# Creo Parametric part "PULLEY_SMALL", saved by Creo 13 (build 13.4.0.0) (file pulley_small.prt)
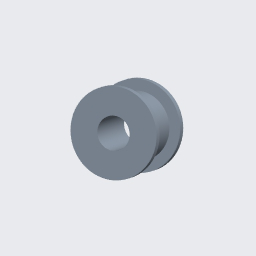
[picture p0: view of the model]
Units: millimeter Newton Second (mmNs); MM, TONNE, SECS

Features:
  1. datum plane "RIGHT"
  2. datum plane "TOP"
  3. datum plane "FRONT"
  4. coordinate system
  5. protrusion
  6. protrusion
  7. protrusion
  8. cut

Surfaces: 4 cylinder, 4 plane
